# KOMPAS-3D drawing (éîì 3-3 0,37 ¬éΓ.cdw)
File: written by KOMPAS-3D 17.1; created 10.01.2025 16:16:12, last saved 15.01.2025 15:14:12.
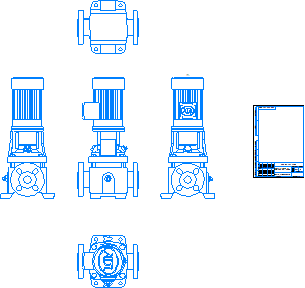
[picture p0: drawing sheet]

Sheet 1: A4, portrait

Title block, sheet 1: name: ВМН 3-3 0,37 кВт; designation: ВМН 3-3 0,37 кВт; material: Сталь 10  ГОСТ 1050-2013; mass: 63,56; sheets: 1; sheet format: A4; stored path: \\adlc.lan\data\АДЛ_ПКД\3D-модели\ADL production\Насосы ГРАНПАМП\Насосы ВМН\ВМН3\KOMPAS 3D\3-3 0,37 кВт _ ВМН.cdw

Views: Проекционный вид 2, Проекционный вид 3, Проекционный вид 4, Проекционный вид 5
Referenced files in \\adlc.lan\data\АДЛ_ПКД\3D-модели\ADL production\Насосы ГРАНПАМП\Насосы ВМН\ВМН3\KOMPAS 3D\: ВМН 3-3 0,37 кВт.m3d
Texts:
  Andrey
  АДЛ
Dimensions and other numbers on the sheet: 1:1; 1; 63,56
